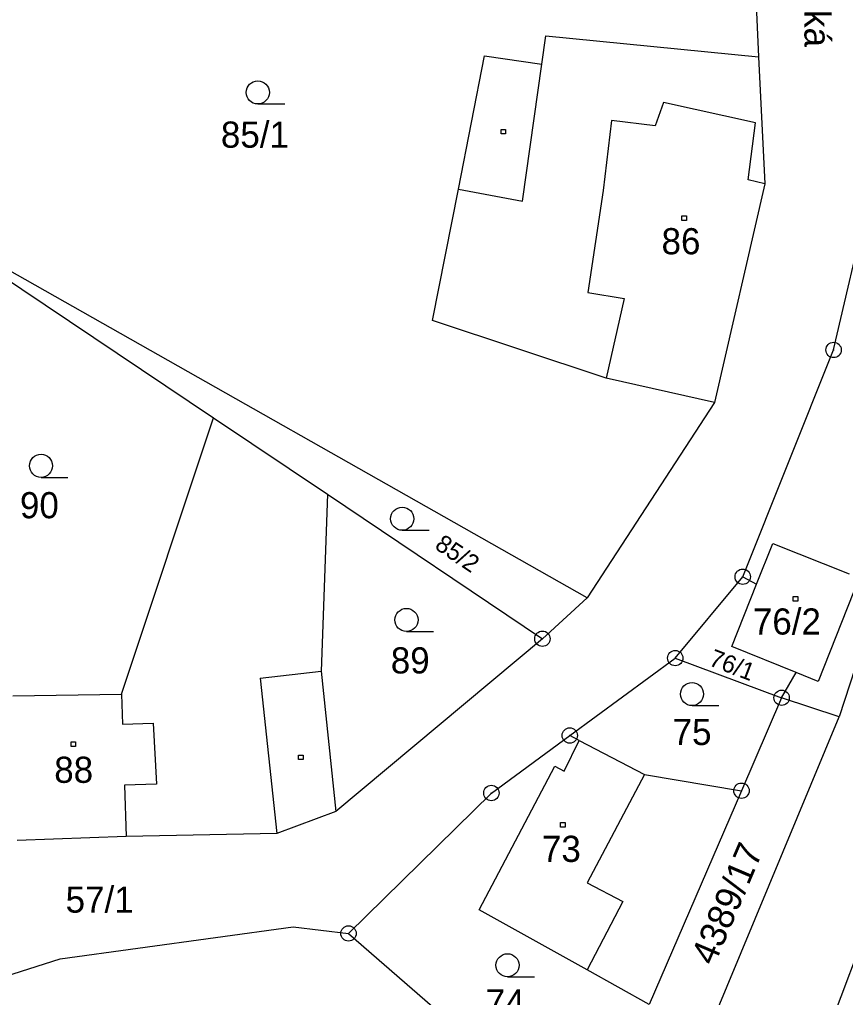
# Model space of a CAD drawing. Extents: x -468021 to -466942, y -1130484 to -1128584.
# Drawn here: x -467240.9 to -467187.2, y -1128822 to -1128758.5 of the extents above; entities that cross this region are included whole.
import ezdxf

# ---------------------------------------------------------------- set-up
doc = ezdxf.new("R2010")
doc.units = 0
doc.layers.add('DKM', color=7, linetype='Continuous')

msp = doc.modelspace()

# ---------------------------------------------------------------- linework, layer by layer
at = {"layer": 'DKM'}
for p, q in [((-467193.35, -1128750.21), (-467192.83, -1128760.89)), ((-467206.92, -1128761.36), (-467206.66, -1128759.52)), ((-467206.66, -1128759.52), (-467192.83, -1128760.89)), ((-467212.35, -1128769.5), (-467210.65, -1128760.82)), ((-467210.65, -1128760.82), (-467206.92, -1128761.36)), ((-467192.83, -1128760.89), (-467192.42, -1128769.14)), ((-467208.19, -1128770.28), (-467206.92, -1128761.36)), ((-467225.4, -1128763.96), (-467223.65, -1128763.96)), ((-467199.02, -1128763.87), (-467199.56, -1128765.38)), ((-467193.02, -1128765.19), (-467199.02, -1128763.87)), ((-467202.39, -1128765.04), (-467202.93, -1128769.59)), ((-467199.56, -1128765.38), (-467202.39, -1128765.04)), ((-467193.5, -1128768.89), (-467193.02, -1128765.19)), ((-467187.95, -1128779.95), (-467184.56, -1128765.34)), ((-467209.58, -1128765.61), (-467209.28, -1128765.61)), ((-467209.58, -1128765.91), (-467209.58, -1128765.61)), ((-467209.28, -1128765.91), (-467209.58, -1128765.91)), ((-467209.28, -1128765.61), (-467209.28, -1128765.91)), ((-467192.42, -1128769.14), (-467195.69, -1128783.36)), ((-467192.42, -1128769.14), (-467193.5, -1128768.89)), ((-467214.03, -1128778.03), (-467212.35, -1128769.5)), ((-467212.35, -1128769.5), (-467208.19, -1128770.28)), ((-467202.93, -1128769.59), (-467203.94, -1128776.21)), ((-467203.97, -1128796.07), (-467247.76, -1128771.29)), ((-467247.76, -1128771.29), (-467228.28, -1128784.36)), ((-467197.82, -1128771.23), (-467197.52, -1128771.23)), ((-467197.82, -1128771.53), (-467197.82, -1128771.23)), ((-467197.52, -1128771.53), (-467197.82, -1128771.53)), ((-467197.52, -1128771.23), (-467197.52, -1128771.53)), ((-467203.94, -1128776.21), (-467201.58, -1128776.61)), ((-467201.58, -1128776.61), (-467202.75, -1128781.79)), ((-467202.75, -1128781.79), (-467214.03, -1128778.03)), ((-467193.86, -1128794.69), (-467187.95, -1128779.95)), ((-467195.69, -1128783.36), (-467202.75, -1128781.79)), ((-467195.69, -1128783.36), (-467203.97, -1128796.07)), ((-467234.26, -1128802.32), (-467228.28, -1128784.36)), ((-467228.28, -1128784.36), (-467220.87, -1128789.33)), ((-467239.5, -1128788.23), (-467237.75, -1128788.23)), ((-467220.87, -1128789.33), (-467221.29, -1128800.83)), ((-467220.87, -1128789.33), (-467206.89, -1128798.72)), ((-467216.01, -1128791.67), (-467214.26, -1128791.67)), ((-467192.97, -1128795.18), (-467191.91, -1128792.53)), ((-467191.91, -1128792.53), (-467186.94, -1128794.5)), ((-467198.25, -1128799.98), (-467193.86, -1128794.69)), ((-467194.58, -1128799.22), (-467192.97, -1128795.18)), ((-467193.86, -1128794.69), (-467192.97, -1128795.18)), ((-467186.28, -1128794.76), (-467188.95, -1128801.5)), ((-467203.97, -1128796.07), (-467206.89, -1128798.72)), ((-467190.58, -1128795.97), (-467190.28, -1128795.97)), ((-467190.58, -1128796.27), (-467190.58, -1128795.97)), ((-467190.28, -1128796.27), (-467190.58, -1128796.27)), ((-467190.28, -1128795.97), (-467190.28, -1128796.27)), ((-467215.73, -1128798.25), (-467213.98, -1128798.25)), ((-467206.89, -1128798.72), (-467220.32, -1128809.95)), ((-467185.85, -1128798.5), (-467187.58, -1128803.79)), ((-467190.39, -1128800.92), (-467194.58, -1128799.22)), ((-467205.11, -1128805.01), (-467198.25, -1128799.98)), ((-467198.25, -1128799.98), (-467191.33, -1128802.56)), ((-467225.25, -1128801.29), (-467221.29, -1128800.83)), ((-467221.29, -1128800.83), (-467220.32, -1128809.95)), ((-467191.33, -1128802.56), (-467190.39, -1128800.92)), ((-467188.95, -1128801.5), (-467190.39, -1128800.92)), ((-467225.25, -1128801.29), (-467224.17, -1128811.38)), ((-467241.34, -1128802.44), (-467234.26, -1128802.32)), ((-467234.26, -1128802.32), (-467234.2, -1128804.27)), ((-467191.33, -1128802.56), (-467193.94, -1128808.6)), ((-467187.58, -1128803.79), (-467191.33, -1128802.56)), ((-467197.16, -1128803.07), (-467195.41, -1128803.07)), ((-467199.87, -1128833.26), (-467187.58, -1128803.79)), ((-467234.2, -1128804.27), (-467232.2, -1128804.21)), ((-467232.2, -1128804.21), (-467231.99, -1128808.18)), ((-467237.55, -1128805.42), (-467237.25, -1128805.42)), ((-467237.55, -1128805.72), (-467237.55, -1128805.42)), ((-467237.25, -1128805.42), (-467237.25, -1128805.72)), ((-467210.21, -1128808.75), (-467205.11, -1128805.01)), ((-467205.48, -1128807.33), (-467204.5, -1128805.33)), ((-467204.5, -1128805.33), (-467205.11, -1128805.01)), ((-467204.5, -1128805.33), (-467200.26, -1128807.54)), ((-467237.25, -1128805.72), (-467237.55, -1128805.72)), ((-467222.75, -1128806.28), (-467222.45, -1128806.28)), ((-467222.75, -1128806.58), (-467222.75, -1128806.28)), ((-467222.45, -1128806.58), (-467222.75, -1128806.58)), ((-467222.45, -1128806.28), (-467222.45, -1128806.58)), ((-467211.01, -1128816.34), (-467206.09, -1128807.01)), ((-467206.09, -1128807.01), (-467205.48, -1128807.33)), ((-467200.26, -1128807.54), (-467203.98, -1128814.58)), ((-467200.26, -1128807.54), (-467193.94, -1128808.6)), ((-467182.01, -1128807.39), (-467190.28, -1128829.48)), ((-467231.99, -1128808.18), (-467234.07, -1128808.25)), ((-467234.07, -1128808.25), (-467233.97, -1128811.57)), ((-467219.5, -1128817.88), (-467210.21, -1128808.75)), ((-467193.94, -1128808.6), (-467199.95, -1128822.49)), ((-467220.32, -1128809.95), (-467224.17, -1128811.38)), ((-467205.71, -1128810.67), (-467205.41, -1128810.67)), ((-467205.71, -1128810.97), (-467205.71, -1128810.67)), ((-467205.41, -1128810.97), (-467205.71, -1128810.97)), ((-467205.41, -1128810.67), (-467205.41, -1128810.97)), ((-467233.97, -1128811.57), (-467241.06, -1128811.84)), ((-467224.17, -1128811.38), (-467233.97, -1128811.57)), ((-467203.98, -1128814.58), (-467201.65, -1128815.81)), ((-467201.65, -1128815.81), (-467203.98, -1128820.25)), ((-467203.98, -1128820.25), (-467211.01, -1128816.34)), ((-467238.26, -1128819.53), (-467223.1, -1128817.44)), ((-467223.1, -1128817.44), (-467219.5, -1128817.88)), ((-467219.5, -1128817.88), (-467203.83, -1128831.47)), ((-467249.69, -1128823.18), (-467238.26, -1128819.53)), ((-467199.95, -1128822.49), (-467203.98, -1128820.25)), ((-467209.16, -1128820.7), (-467207.41, -1128820.7))]:
    msp.add_line(p, q, dxfattribs=at)
for centre, radius in [((-467225.4, -1128763.21), 0.75), ((-467187.95, -1128779.95), 0.5), ((-467187.95, -1128779.95), 0.01), ((-467239.5, -1128787.48), 0.75), ((-467216.01, -1128790.92), 0.75), ((-467193.86, -1128794.69), 0.5), ((-467193.86, -1128794.69), 0.01), ((-467215.73, -1128797.5), 0.75), ((-467206.89, -1128798.72), 0.5), ((-467206.89, -1128798.72), 0.01), ((-467198.25, -1128799.98), 0.5), ((-467198.25, -1128799.98), 0.01), ((-467197.16, -1128802.32), 0.75), ((-467191.33, -1128802.56), 0.5), ((-467191.33, -1128802.56), 0.01), ((-467205.11, -1128805.01), 0.5), ((-467205.11, -1128805.01), 0.01), ((-467210.21, -1128808.75), 0.5), ((-467193.94, -1128808.6), 0.5), ((-467193.94, -1128808.6), 0.01), ((-467210.21, -1128808.75), 0.01), ((-467219.5, -1128817.88), 0.5), ((-467219.5, -1128817.88), 0.01), ((-467209.16, -1128819.95), 0.75)]:
    msp.add_circle(centre, radius, dxfattribs=at)

# ---------------------------------------------------------------- texts
for s, height, rotation, p in [('Lubenská', 1.7, 270.45099, (-467189.917, -1128750.401)), ('85/2', 1.14, 325.93905, (-467213.96, -1128792.82)), ('76/1', 1.14, 339.15204, (-467196.13, -1128800.43)), ('4389/17', 1.7, 66.92328, (-467195.72, -1128820.04))]:
    msp.add_text(s, height=height, rotation=rotation, dxfattribs=at).set_placement(p)
for s, p in [('85/1', (-467227.8, -1128766.8)), ('86', (-467199.14, -1128773.73)), ('90', (-467240.87, -1128790.89)), ('76/2', (-467193.2, -1128798.45)), ('89', (-467216.75, -1128800.98)), ('75', (-467198.42, -1128805.63)), ('88', (-467238.64, -1128808.09)), ('73', (-467206.92, -1128813.23)), ('57/1', (-467237.9, -1128816.53)), ('74', (-467210.58, -1128823.21))]:
    msp.add_text(s, height=1.7, dxfattribs=at).set_placement(p)

doc.saveas('drawing.dxf')
